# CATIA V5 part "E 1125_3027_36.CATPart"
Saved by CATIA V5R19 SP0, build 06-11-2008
Nomenclature: E 1125_30-27_36
Description: PART-E 1125_30-27_36-DESC
Property "Hersteller": "Meusburger"
Property "Material": "2.0598 200 HB / Graphit _ graphite"
Property "Bestellnummer": "E 1125/30-27/36"
Property "Teilenummer": "E 1125/30-27/36"
Property "Beschreibung": "Führungsbuchse für Auswerferpaket, wartungsfrei _ Guide bush for ejector set, self lubricating"
Material "Brass": density 8216 kg/m3, Young's modulus 1.31e+11 Pa, Poisson ratio 0.35, thermal expansion 1.67e-05 1/K
Bounding box of the stored display mesh (mm): x -20.5 to 20.5, y -20.49 to 20.49, z -36 to 27
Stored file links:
  G:\UTB\Kombinované\Bakalářská práce\Catia\FORMA\E 1125_3027_36.CATPart
  D:\Aplikace\CATIA\Nová složka\win_b64\startup\materials\Catalog.CATMaterial
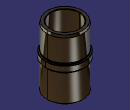
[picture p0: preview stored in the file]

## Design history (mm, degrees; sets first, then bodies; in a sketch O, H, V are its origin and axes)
Body1 "E 1125_30-27_36" (main body)
  Solid1: solid without history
